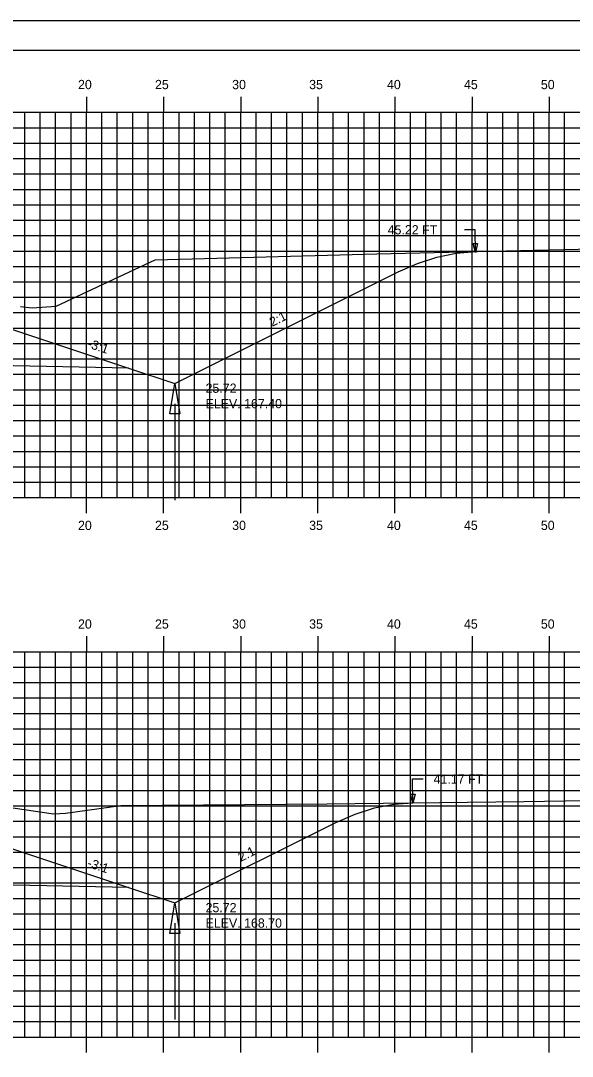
# Model space of a CAD drawing. Extents: x 1140537 to 1140707, y 608981 to 609091.
# Drawn here: x 1140636 to 1140671.7, y 609024.1 to 609091.3 of the extents above; entities that cross this region are included whole.
import ezdxf

# ---------------------------------------------------------------- set-up
doc = ezdxf.new("R2010")
doc.units = 0
for name, color, linetype in [('ANNOTATION', 7, 'Continuous'), ('BORDER', 7, 'Continuous'), ('D_Drainage_Ditch_Line', 7, 'Continuous'), ('D_Roadway_SlopeLines', 7, 'Continuous'), ('D_Roadway_SubGrade', 7, 'Continuous'), ('D_Text_Standard', 7, 'Continuous'), ('H_V ANNOTATION', 7, 'Continuous'), ('MAJOR', 7, 'Continuous'), ('MINOR', 7, 'Continuous'), ('PLOT BOUNDARY', 7, 'Continuous'), ('S_Roadway_Centerline', 7, 'Continuous')]:
    doc.layers.add(name, color=color, linetype=linetype)

msp = doc.modelspace()

# ---------------------------------------------------------------- linework, layer by layer
for points in [[(1140587.473, 609071.258), (1140594.52, 609067.734), (1140597.52, 609068.734), (1140605.244, 609071.309), (1140605.245, 609071.309), (1140609.245, 609071.469), (1140620.245, 609071.689), (1140631.245, 609071.469), (1140635.245, 609071.309), (1140642.968, 609068.735), (1140645.968, 609067.735), (1140660.465, 609074.983), (1140661.715, 609075.533), (1140662.965, 609075.935), (1140664.215, 609076.188), (1140665.465, 609076.292)], [(1140586.756, 609036.254), (1140588.006, 609036.356), (1140589.256, 609036.25), (1140590.506, 609035.937), (1140591.756, 609035.416), (1140594.52, 609034.034), (1140597.52, 609035.034), (1140605.244, 609037.608), (1140605.245, 609037.608), (1140609.245, 609037.768), (1140620.245, 609037.988), (1140631.245, 609037.768), (1140635.245, 609037.608), (1140642.968, 609035.034), (1140645.968, 609034.034), (1140656.415, 609039.257), (1140657.665, 609039.806), (1140658.915, 609040.202), (1140660.165, 609040.445), (1140661.415, 609040.536)]]:
    msp.add_lwpolyline(points)
at = {"layer": 'BORDER'}
msp.add_lwpolyline([(1140545.245, 608984.335), (1140705.245, 608984.335), (1140705.245, 609089.335), (1140545.245, 609089.335)], close=True, dxfattribs=at)
at = {"layer": 'D_Drainage_Ditch_Line'}
for p, q in [((1140645.968, 609066.422), (1140645.968, 609060.179)), ((1140645.968, 609032.721), (1140645.968, 609026.478))]:
    msp.add_line(p, q, dxfattribs=at)
for points in [[(1140646.296, 609065.766), (1140645.64, 609065.766), (1140645.968, 609067.735)], [(1140646.296, 609032.065), (1140645.64, 609032.065), (1140645.968, 609034.034)]]:
    msp.add_lwpolyline(points, close=True, dxfattribs=at)
at = {"layer": 'D_Roadway_SlopeLines'}
for points in [[(1140645.968, 609067.735), (1140660.465, 609074.983), (1140661.715, 609075.533), (1140662.965, 609075.935), (1140664.215, 609076.188), (1140665.465, 609076.292)], [(1140642.968, 609068.735), (1140645.968, 609067.735)], [(1140645.968, 609034.034), (1140656.415, 609039.257), (1140657.665, 609039.806), (1140658.915, 609040.202), (1140660.165, 609040.445), (1140661.415, 609040.536)], [(1140642.968, 609035.034), (1140645.968, 609034.034)]]:
    msp.add_lwpolyline(points, dxfattribs=at)
at = {"layer": 'D_Roadway_SubGrade'}
for points in [[(1140631.245, 609071.052), (1140631.245, 609071.219), (1140635.245, 609071.059), (1140635.245, 609071.309), (1140635.245, 609071.309), (1140642.968, 609068.735), (1140631.245, 609068.969)], [(1140631.245, 609037.351), (1140631.245, 609037.518), (1140635.245, 609037.358), (1140635.245, 609037.608), (1140635.245, 609037.608), (1140642.968, 609035.034), (1140631.245, 609035.268)]]:
    msp.add_lwpolyline(points, close=True, dxfattribs=at)
at = {"layer": 'D_Text_Standard'}
for points in [[(1140665.465, 609076.233), (1140665.439, 609077.711), (1140664.759, 609077.711)], [(1140661.415, 609040.507), (1140661.395, 609042.08), (1140662.075, 609042.08)]]:
    msp.add_lwpolyline(points, dxfattribs=at)
for points in [[(1140665.465, 609076.233), (1140665.309, 609076.812), (1140665.6, 609076.817)], [(1140661.415, 609040.507), (1140661.262, 609041.087), (1140661.553, 609041.091)]]:
    msp.add_lwpolyline(points, close=True, dxfattribs=at)
at = {"layer": 'MAJOR'}
for p, q in [((1140640.245, 609086.337), (1140640.245, 609085.335)), ((1140645.245, 609086.337), (1140645.245, 609085.335)), ((1140650.245, 609086.337), (1140650.245, 609085.335)), ((1140655.245, 609086.337), (1140655.245, 609085.335)), ((1140660.245, 609086.337), (1140660.245, 609085.335)), ((1140665.245, 609086.337), (1140665.245, 609085.335)), ((1140670.245, 609086.337), (1140670.245, 609085.335)), ((1140550.245, 609085.335), (1140690.245, 609085.335)), ((1140550.245, 609085.335), (1140690.245, 609085.335)), ((1140640.245, 609060.335), (1140640.245, 609085.335)), ((1140645.245, 609060.335), (1140645.245, 609085.335)), ((1140650.245, 609060.335), (1140650.245, 609085.335)), ((1140655.245, 609060.335), (1140655.245, 609085.335)), ((1140660.245, 609060.335), (1140660.245, 609085.335)), ((1140665.245, 609060.335), (1140665.245, 609085.335)), ((1140670.245, 609060.335), (1140670.245, 609085.335)), ((1140550.245, 609080.335), (1140690.245, 609080.335)), ((1140550.245, 609075.335), (1140690.245, 609075.335)), ((1140550.245, 609070.335), (1140690.245, 609070.335)), ((1140550.245, 609065.335), (1140690.245, 609065.335)), ((1140550.245, 609060.335), (1140690.245, 609060.335)), ((1140550.245, 609060.335), (1140690.245, 609060.335)), ((1140640.245, 609059.333), (1140640.245, 609060.335)), ((1140645.245, 609059.333), (1140645.245, 609060.335)), ((1140650.245, 609059.333), (1140650.245, 609060.335)), ((1140655.245, 609059.333), (1140655.245, 609060.335)), ((1140660.245, 609059.333), (1140660.245, 609060.335)), ((1140665.245, 609059.333), (1140665.245, 609060.335)), ((1140670.245, 609059.333), (1140670.245, 609060.335)), ((1140640.245, 609051.337), (1140640.245, 609050.335)), ((1140645.245, 609051.337), (1140645.245, 609050.335)), ((1140650.245, 609051.337), (1140650.245, 609050.335)), ((1140655.245, 609051.337), (1140655.245, 609050.335)), ((1140660.245, 609051.337), (1140660.245, 609050.335)), ((1140665.245, 609051.337), (1140665.245, 609050.335)), ((1140670.245, 609051.337), (1140670.245, 609050.335)), ((1140550.245, 609050.335), (1140690.245, 609050.335)), ((1140550.245, 609050.335), (1140690.245, 609050.335)), ((1140640.245, 609025.335), (1140640.245, 609050.335)), ((1140645.245, 609025.335), (1140645.245, 609050.335)), ((1140650.245, 609025.335), (1140650.245, 609050.335)), ((1140655.245, 609025.335), (1140655.245, 609050.335)), ((1140660.245, 609025.335), (1140660.245, 609050.335)), ((1140665.245, 609025.335), (1140665.245, 609050.335)), ((1140670.245, 609025.335), (1140670.245, 609050.335)), ((1140550.245, 609045.335), (1140690.245, 609045.335)), ((1140550.245, 609040.335), (1140690.245, 609040.335)), ((1140550.245, 609035.335), (1140690.245, 609035.335)), ((1140550.245, 609030.335), (1140690.245, 609030.335)), ((1140550.245, 609025.335), (1140690.245, 609025.335)), ((1140550.245, 609025.335), (1140690.245, 609025.335)), ((1140640.245, 609024.333), (1140640.245, 609025.335)), ((1140645.245, 609024.333), (1140645.245, 609025.335)), ((1140650.245, 609024.333), (1140650.245, 609025.335)), ((1140655.245, 609024.333), (1140655.245, 609025.335)), ((1140660.245, 609024.333), (1140660.245, 609025.335)), ((1140665.245, 609024.333), (1140665.245, 609025.335)), ((1140670.245, 609024.333), (1140670.245, 609025.335))]:
    msp.add_line(p, q, dxfattribs=at)
at = {"layer": 'MINOR'}
for p, q in [((1140636.245, 609060.335), (1140636.245, 609085.335)), ((1140637.245, 609060.335), (1140637.245, 609085.335)), ((1140638.245, 609060.335), (1140638.245, 609085.335)), ((1140639.245, 609060.335), (1140639.245, 609085.335)), ((1140641.245, 609060.335), (1140641.245, 609085.335)), ((1140642.245, 609060.335), (1140642.245, 609085.335)), ((1140643.245, 609060.335), (1140643.245, 609085.335)), ((1140644.245, 609060.335), (1140644.245, 609085.335)), ((1140646.245, 609060.335), (1140646.245, 609085.335)), ((1140647.245, 609060.335), (1140647.245, 609085.335)), ((1140648.245, 609060.335), (1140648.245, 609085.335)), ((1140649.245, 609060.335), (1140649.245, 609085.335)), ((1140651.245, 609060.335), (1140651.245, 609085.335)), ((1140652.245, 609060.335), (1140652.245, 609085.335)), ((1140653.245, 609060.335), (1140653.245, 609085.335)), ((1140654.245, 609060.335), (1140654.245, 609085.335)), ((1140656.245, 609060.335), (1140656.245, 609085.335)), ((1140657.245, 609060.335), (1140657.245, 609085.335)), ((1140658.245, 609060.335), (1140658.245, 609085.335)), ((1140659.245, 609060.335), (1140659.245, 609085.335)), ((1140661.245, 609060.335), (1140661.245, 609085.335)), ((1140662.245, 609060.335), (1140662.245, 609085.335)), ((1140663.245, 609060.335), (1140663.245, 609085.335)), ((1140664.245, 609060.335), (1140664.245, 609085.335)), ((1140666.245, 609060.335), (1140666.245, 609085.335)), ((1140667.245, 609060.335), (1140667.245, 609085.335)), ((1140668.245, 609060.335), (1140668.245, 609085.335)), ((1140669.245, 609060.335), (1140669.245, 609085.335)), ((1140671.245, 609060.335), (1140671.245, 609085.335)), ((1140550.245, 609084.335), (1140690.245, 609084.335)), ((1140550.245, 609083.335), (1140690.245, 609083.335)), ((1140550.245, 609082.335), (1140690.245, 609082.335)), ((1140550.245, 609081.335), (1140690.245, 609081.335)), ((1140550.245, 609079.335), (1140690.245, 609079.335)), ((1140550.245, 609078.335), (1140690.245, 609078.335)), ((1140550.245, 609077.335), (1140690.245, 609077.335)), ((1140550.245, 609076.335), (1140690.245, 609076.335)), ((1140550.245, 609074.335), (1140690.245, 609074.335)), ((1140550.245, 609073.335), (1140690.245, 609073.335)), ((1140550.245, 609072.335), (1140690.245, 609072.335)), ((1140550.245, 609071.335), (1140690.245, 609071.335)), ((1140550.245, 609069.335), (1140690.245, 609069.335)), ((1140550.245, 609068.335), (1140690.245, 609068.335)), ((1140550.245, 609067.335), (1140690.245, 609067.335)), ((1140550.245, 609066.335), (1140690.245, 609066.335)), ((1140550.245, 609064.335), (1140690.245, 609064.335)), ((1140550.245, 609063.335), (1140690.245, 609063.335)), ((1140550.245, 609062.335), (1140690.245, 609062.335)), ((1140550.245, 609061.335), (1140690.245, 609061.335)), ((1140636.245, 609025.335), (1140636.245, 609050.335)), ((1140637.245, 609025.335), (1140637.245, 609050.335)), ((1140638.245, 609025.335), (1140638.245, 609050.335)), ((1140639.245, 609025.335), (1140639.245, 609050.335)), ((1140641.245, 609025.335), (1140641.245, 609050.335)), ((1140642.245, 609025.335), (1140642.245, 609050.335)), ((1140643.245, 609025.335), (1140643.245, 609050.335)), ((1140644.245, 609025.335), (1140644.245, 609050.335)), ((1140646.245, 609025.335), (1140646.245, 609050.335)), ((1140647.245, 609025.335), (1140647.245, 609050.335)), ((1140648.245, 609025.335), (1140648.245, 609050.335)), ((1140649.245, 609025.335), (1140649.245, 609050.335)), ((1140651.245, 609025.335), (1140651.245, 609050.335)), ((1140652.245, 609025.335), (1140652.245, 609050.335)), ((1140653.245, 609025.335), (1140653.245, 609050.335)), ((1140654.245, 609025.335), (1140654.245, 609050.335)), ((1140656.245, 609025.335), (1140656.245, 609050.335)), ((1140657.245, 609025.335), (1140657.245, 609050.335)), ((1140658.245, 609025.335), (1140658.245, 609050.335)), ((1140659.245, 609025.335), (1140659.245, 609050.335)), ((1140661.245, 609025.335), (1140661.245, 609050.335)), ((1140662.245, 609025.335), (1140662.245, 609050.335)), ((1140663.245, 609025.335), (1140663.245, 609050.335)), ((1140664.245, 609025.335), (1140664.245, 609050.335)), ((1140666.245, 609025.335), (1140666.245, 609050.335)), ((1140667.245, 609025.335), (1140667.245, 609050.335)), ((1140668.245, 609025.335), (1140668.245, 609050.335)), ((1140669.245, 609025.335), (1140669.245, 609050.335)), ((1140671.245, 609025.335), (1140671.245, 609050.335)), ((1140550.245, 609049.335), (1140690.245, 609049.335)), ((1140550.245, 609048.335), (1140690.245, 609048.335)), ((1140550.245, 609047.335), (1140690.245, 609047.335)), ((1140550.245, 609046.335), (1140690.245, 609046.335)), ((1140550.245, 609044.335), (1140690.245, 609044.335)), ((1140550.245, 609043.335), (1140690.245, 609043.335)), ((1140550.245, 609042.335), (1140690.245, 609042.335)), ((1140550.245, 609041.335), (1140690.245, 609041.335)), ((1140550.245, 609039.335), (1140690.245, 609039.335)), ((1140550.245, 609038.335), (1140690.245, 609038.335)), ((1140550.245, 609037.335), (1140690.245, 609037.335)), ((1140550.245, 609036.335), (1140690.245, 609036.335)), ((1140550.245, 609034.335), (1140690.245, 609034.335)), ((1140550.245, 609033.335), (1140690.245, 609033.335)), ((1140550.245, 609032.335), (1140690.245, 609032.335)), ((1140550.245, 609031.335), (1140690.245, 609031.335)), ((1140550.245, 609029.335), (1140690.245, 609029.335)), ((1140550.245, 609028.335), (1140690.245, 609028.335)), ((1140550.245, 609027.335), (1140690.245, 609027.335)), ((1140550.245, 609026.335), (1140690.245, 609026.335))]:
    msp.add_line(p, q, dxfattribs=at)
at = {"layer": 'PLOT BOUNDARY'}
msp.add_lwpolyline([(1140537.151, 608981.276), (1140707.151, 608981.276), (1140707.151, 609091.276), (1140537.151, 609091.276)], close=True, dxfattribs=at)
at = {"layer": 'S_Roadway_Centerline'}
for points in [[(1140635.963, 609072.743), (1140636.719, 609072.645), (1140638.275, 609072.761), (1140644.695, 609075.761), (1140659.062, 609076.141), (1140675.851, 609076.536), (1140683.575, 609076.463), (1140690.245, 609076.267)], [(1140635.028, 609040.273), (1140638.111, 609039.824), (1140638.885, 609039.859), (1140642.483, 609040.354), (1140655.858, 609040.472), (1140668.593, 609040.618), (1140688.858, 609040.948), (1140690.245, 609040.968)]]:
    msp.add_lwpolyline(points, dxfattribs=at)

# ---------------------------------------------------------------- texts
at = {"layer": 'ANNOTATION'}
for s, rotation, p in [('2:1', 26.56505, (1140652.289, 609071.413)), ('-3:1', 341.56521, (1140640.256, 609070.093)), ('2:1', 26.56505, (1140650.264, 609036.7)), ('-3:1', 341.56521, (1140640.256, 609036.392))]:
    msp.add_text(s, height=0.6, rotation=rotation, dxfattribs=at).set_placement(p)
at = {"layer": 'D_Text_Standard'}
for s, p in [('45.22 FT', (1140659.775, 609077.411)), ('25.72', (1140647.968, 609067.135)), ('ELEV. 167.40', (1140647.968, 609066.133)), ('41.17 FT', (1140662.755, 609041.78)), ('25.72', (1140647.968, 609033.434)), ('ELEV. 168.70', (1140647.968, 609032.432))]:
    msp.add_text(s, height=0.6, dxfattribs=at).set_placement(p)
at = {"layer": 'H_V ANNOTATION'}
for s, p in [('20', (1140639.698, 609086.835)), ('25', (1140644.69, 609086.835)), ('30', (1140649.693, 609086.835)), ('35', (1140654.685, 609086.835)), ('40', (1140659.731, 609086.835)), ('45', (1140664.723, 609086.835)), ('50', (1140669.709, 609086.835)), ('20', (1140639.698, 609058.235)), ('25', (1140644.69, 609058.235)), ('30', (1140649.693, 609058.235)), ('35', (1140654.685, 609058.235)), ('40', (1140659.731, 609058.235)), ('45', (1140664.723, 609058.235)), ('50', (1140669.709, 609058.235)), ('20', (1140639.698, 609051.835)), ('25', (1140644.69, 609051.835)), ('30', (1140649.693, 609051.835)), ('35', (1140654.685, 609051.835)), ('40', (1140659.731, 609051.835)), ('45', (1140664.723, 609051.835)), ('50', (1140669.709, 609051.835))]:
    msp.add_text(s, height=0.6, dxfattribs=at).set_placement(p)

doc.saveas('drawing.dxf')
